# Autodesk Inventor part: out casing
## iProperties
Created: 2009-01
Part Number: out casing
Document SubType Name: Modeling
Designer: pmulligan
Density: 1 g/cm^3
Author: pmulligan
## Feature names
1. Revolution1
2. Extrusion1
3. Extrusion2
4. Extrusion3
5. Extrusion4
6. Chamfer1
7. Extrusion5
8. Chamfer2
9. Chamfer3
10. Chamfer4
